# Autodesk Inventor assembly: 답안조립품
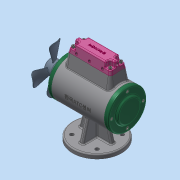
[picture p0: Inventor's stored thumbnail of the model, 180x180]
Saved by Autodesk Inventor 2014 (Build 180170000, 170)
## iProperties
Created: 2023-01
Part Number: 답안조립품
Document SubType Name: Assembly
Designer: dg
Author: dg
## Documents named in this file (19)
- C:\Users\dg\Desktop\630106V1019\답안조립품.iam
- C:\Users\dg\Desktop\630106V1019\본체.ipt
- C:\Users\dg\Desktop\630106V1019\가변스프링.ipt
- C:\Users\dg\Desktop\630106V1019\뒤커버.ipt
- C:\Users\dg\Desktop\630106V1019\멈춤나사 M4 x 8.ipt
- C:\Users\dg\Desktop\630106V1019\베어링 6203.ipt
- C:\Users\dg\Desktop\630106V1019\볼트 M4 x 12.ipt
- C:\Users\dg\Desktop\630106V1019\볼트 M4 x 16.ipt
- C:\Users\dg\Desktop\630106V1019\부시.ipt
- C:\Users\dg\Desktop\630106V1019\슬라이드.ipt
- C:\Users\dg\Desktop\630106V1019\앞커버.ipt
- C:\Users\dg\Desktop\630106V1019\오일실 17 30 8.ipt
- C:\Users\dg\Desktop\630106V1019\축.ipt
- C:\Users\dg\Desktop\630106V1019\키 5 x 5 x 18.ipt
- C:\Users\dg\Desktop\630106V1019\팬날개.ipt
- 팬날개.ipt
- C:\Users\dg\Desktop\630106V1019\헤더커버.ipt
- C:\Users\dg\Desktop\630106V1019\가변스프링2.ipt
- C:\Users\dg\Desktop\630106V1019\가변스프링3.ipt
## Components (4 placed, 4 different names)
1. 가변스프링:1
2. 헤더커버:1
3. 가변스프링2:1
4. 가변스프링3:1
